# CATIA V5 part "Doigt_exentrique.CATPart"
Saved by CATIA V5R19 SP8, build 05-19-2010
Part number: Doigt exentrique
Publications: "Esquisse.4"
Bounding box of the stored display mesh (mm): x -23.5 to -4, y 10 to 18, z -4 to 4
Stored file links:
  C:\Users\ThinkMotion\Desktop\EU_thinkMotion\iao\IAO_MMS_Groupe3\ecartoux\projet_IAO_ecartoux\projet_IAO_ecartoux\griffe_d'une_camera_ecartoux\Doigt_exentrique.CATPart
  C:\Users\ThinkMotion\Desktop\EU_thinkMotion\iao\IAO_MMS_Groupe3\ecartoux\projet_IAO_ecartoux\projet_IAO_ecartoux\griffe_d'une_camera_ecartoux\Mecanisme_a_coulisse_et_leviers_de_la_griffe_d'un_camera_ecartoux.CATProduct
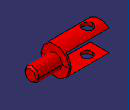
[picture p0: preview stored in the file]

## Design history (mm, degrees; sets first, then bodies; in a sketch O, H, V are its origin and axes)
Set1
  Plane1: linked copy from another document
  Point1: linked copy from another document
  Plane2: linked copy from another document
  Point2: linked copy from another document
  Line1: linked copy from another document
  Point3: linked copy from another document
  Point4: linked copy from another document
  Plane3: linked copy from another document
Body1 (main body)
  Sketch1 on Plane2, origin (0, 14, 0), H (-1, 0, 0), V (0, 0, 1)
    point P1 (11, 5)
    line L1 (11, 5) -> (23.5, 5)
    line L2 (23.5, 5) -> (23.5, 3)
    line L3 (23.5, 3) -> (11.5, 3)
    point P2 (23.5, 5)
    point P3 (23.5, 3)
    point P4 (11.5, 3)
    line L4 (11, 5) -> (11, 0)
    line L5 (11.5, 0) -> (11.5, 3)
    point P5 (11, 5)
    point P6 (11.5, 0)
    point P7 (11, 0)
    reference projected line E1 (4, 0) -> (24, 0) from edge of Line1
    point P10 (11, 0)
    point P11 (11, -5)
    line L6 (11, -5) -> (11, 0)
    point P12 (11.5, -3)
    point P13 (11.5, 0)
    line L7 (11.5, 0) -> (11.5, -3)
    point P14 (23.5, -3)
    line L8 (23.5, -3) -> (11.5, -3)
    point P15 (23.5, -5)
    point P16 (11, -5)
    line L9 (11, -5) -> (23.5, -5)
    line L10 (23.5, -5) -> (23.5, -3)
    reference projected line E2 (4, 0) -> (24, 0) from Line1
    reference projected line E3 (4, 0) -> (24, 0) from Line1
    reference projected point E4 (8, 0) from Point4
    distance L2 L4 = 12.5
    distance L1 L3 = 2
    distance L1 E2 = 5
    distance L5 L4 = 0.5
    distance E4 L4 = 3
    horizontal: L1 H, L3 H
    vertical: L2 V, L4 V, L5 V
    coincidence: P1 P5, P7 E3, P6 P13, P7 P10, P11 P16
    symmetry: P7 P10 E1, P5 P11 E1, L4 L6 E1, P4 P12 E1, P6 P13 E1, L5 L7 E1, P3 P14 E1, L3 L8 E1, P2 P15 E1, P1 P16 E1, L1 L9 E1, L2 L10 E1
  Sketch2 on Plane1, origin (-20, 0, 0), H (0, 1, 0), V (0, 0, 1)
    circle A1 centre (14, 0) radius 4
    point P1 (14, 0)
    reference projected point E1 (14, 0) from Point1
    radius A1 = 4
    coincidence: P1 E1
  SolidCombine1: FirstComponentProfile Sketch1, FirstComponentDirection Sketch1, SecondComponentProfile Sketch2, SecondComponentDirection Sketch2
  Sketch3 on Plane1, origin (-20, 0, 0), H (0, 1, 0), V (0, 0, 1)
    circle A1 centre (14, 0) radius 2
    point P1 (14, 0)
    reference projected point E1 (14, 0) from Point1
    radius A1 = 2
    coincidence: P1 E1
  Pad1: profile Sketch3, direction (-1, 0, 0), length -9, opposite side length 16
  Sketch4 on Plane3, origin (0, 0, 0), H (1, 0, 0), V (0, 1, 0)
    circle A1 centre (-20, 14) radius 1.5
    point P1 (-20, 14)
    reference projected point E1 (-20, 14) from Point2
    radius A1 = 1.5
    coincidence: P1 E1
  Pocket1: profile Sketch4, direction (0, 0, -1), length 4, mirrored extent
  Chamfer1: length 0.5, angle 45, on edge [face of Pad1 from Sketch3.A1 | start face of Pad1]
